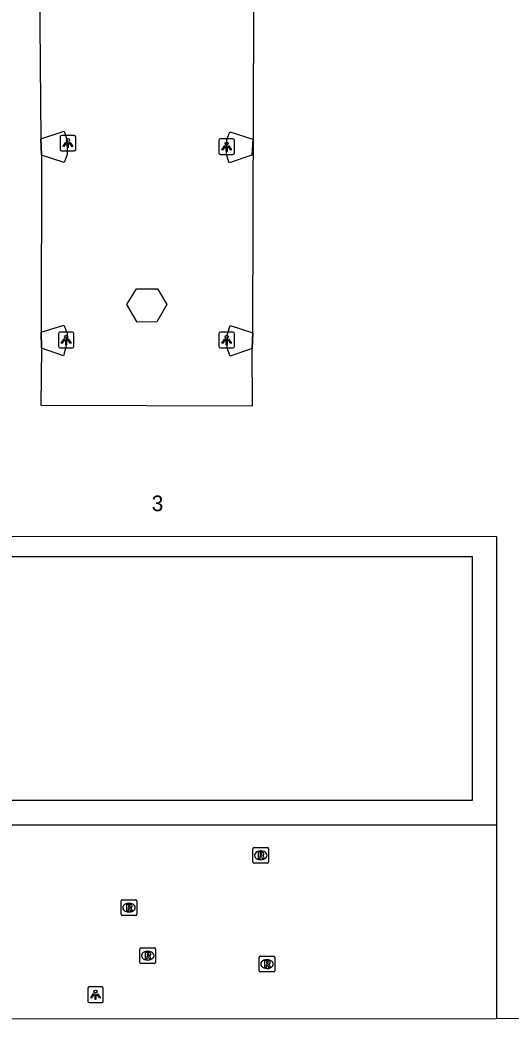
# Model space of a CAD drawing. Extents: x 161477 to 163040, y 383680 to 384868.
# Drawn here: x 161868 to 161899.5, y 384190.9 to 384254.9 of the extents above; entities that cross this region are included whole.
import ezdxf

# ---------------------------------------------------------------- set-up
doc = ezdxf.new("R2010")
doc.units = 0
for name, color, linetype in [('IMGEO_Lichtpunt', 7, 'Continuous'), ('IMGEO_Pand', 7, 'Continuous'), ('IMGEO_Pand_nummerreeks', 7, 'Continuous'), ('IMGEO_Pand_overbouw', 7, 'Continuous'), ('IMGEO_Rioolput', 7, 'Continuous'), ('IMGEO_Voetpad_gesloten', 7, 'Continuous'), ('IMGEO_Voetpad_open', 7, 'Continuous')]:
    doc.layers.add(name, color=color, linetype=linetype)

msp = doc.modelspace()

# ---------------------------------------------------------------- linework, layer by layer
at = {"layer": 'IMGEO_Lichtpunt'}
for p, q in [((161871.519, 384247.498), (161870.711, 384247.498)), ((161871.519, 384247.498), (161870.711, 384247.498)), ((161870.617, 384247.403), (161870.617, 384246.596)), ((161870.617, 384247.403), (161870.617, 384246.596)), ((161871.613, 384246.596), (161871.613, 384247.403)), ((161871.613, 384246.596), (161871.613, 384247.403)), ((161880.787, 384247.183), (161880.787, 384246.376)), ((161880.787, 384247.183), (161880.787, 384246.376)), ((161881.689, 384247.278), (161880.881, 384247.278)), ((161881.689, 384247.278), (161880.881, 384247.278)), ((161881.783, 384246.376), (161881.783, 384247.183)), ((161881.783, 384246.376), (161881.783, 384247.183)), ((161870.711, 384246.502), (161871.519, 384246.502)), ((161870.711, 384246.502), (161871.519, 384246.502)), ((161880.881, 384246.282), (161881.689, 384246.282)), ((161880.881, 384246.282), (161881.689, 384246.282)), ((161870.507, 384234.793), (161870.507, 384233.986)), ((161870.507, 384234.793), (161870.507, 384233.986)), ((161871.409, 384234.888), (161870.601, 384234.888)), ((161871.409, 384234.888), (161870.601, 384234.888)), ((161871.503, 384233.986), (161871.503, 384234.793)), ((161871.503, 384233.986), (161871.503, 384234.793)), ((161880.787, 384234.793), (161880.787, 384233.986)), ((161880.787, 384234.793), (161880.787, 384233.986)), ((161881.689, 384234.888), (161880.881, 384234.888)), ((161881.689, 384234.888), (161880.881, 384234.888)), ((161881.783, 384233.986), (161881.783, 384234.793)), ((161881.783, 384233.986), (161881.783, 384234.793)), ((161870.601, 384233.892), (161871.409, 384233.892)), ((161870.601, 384233.892), (161871.409, 384233.892)), ((161880.881, 384233.892), (161881.689, 384233.892)), ((161880.881, 384233.892), (161881.689, 384233.892)), ((161872.387, 384192.843), (161872.387, 384192.036)), ((161872.387, 384192.843), (161872.387, 384192.036)), ((161873.289, 384192.938), (161872.481, 384192.938)), ((161873.289, 384192.938), (161872.481, 384192.938)), ((161873.383, 384192.036), (161873.383, 384192.843)), ((161873.383, 384192.036), (161873.383, 384192.843)), ((161872.481, 384191.942), (161873.289, 384191.942)), ((161872.481, 384191.942), (161873.289, 384191.942))]:
    msp.add_line(p, q, dxfattribs=at)
for points in [[(161870.991, 384247.067), (161871.03, 384247.039), (161870.842, 384246.777), (161870.804, 384246.804), (161870.991, 384247.067)], [(161871.093, 384247.019), (161871.14, 384247.019), (161871.14, 384246.697), (161871.093, 384246.697), (161871.093, 384247.019)], [(161871.203, 384247.039), (161871.241, 384247.066), (161871.428, 384246.804), (161871.389, 384246.776), (161871.203, 384247.039)], [(161881.161, 384246.847), (161881.2, 384246.819), (161881.012, 384246.557), (161880.974, 384246.584), (161881.161, 384246.847)], [(161881.263, 384246.799), (161881.31, 384246.799), (161881.31, 384246.477), (161881.263, 384246.477), (161881.263, 384246.799)], [(161881.373, 384246.819), (161881.411, 384246.846), (161881.598, 384246.584), (161881.559, 384246.556), (161881.373, 384246.819)], [(161870.881, 384234.457), (161870.92, 384234.429), (161870.732, 384234.167), (161870.694, 384234.194), (161870.881, 384234.457)], [(161870.983, 384234.409), (161871.03, 384234.409), (161871.03, 384234.087), (161870.983, 384234.087), (161870.983, 384234.409)], [(161871.093, 384234.429), (161871.131, 384234.456), (161871.318, 384234.194), (161871.279, 384234.166), (161871.093, 384234.429)], [(161881.161, 384234.457), (161881.2, 384234.429), (161881.012, 384234.167), (161880.974, 384234.194), (161881.161, 384234.457)], [(161881.263, 384234.409), (161881.31, 384234.409), (161881.31, 384234.087), (161881.263, 384234.087), (161881.263, 384234.409)], [(161881.373, 384234.429), (161881.411, 384234.456), (161881.598, 384234.194), (161881.559, 384234.166), (161881.373, 384234.429)], [(161872.761, 384192.507), (161872.8, 384192.479), (161872.612, 384192.217), (161872.574, 384192.244), (161872.761, 384192.507)], [(161872.863, 384192.459), (161872.91, 384192.459), (161872.91, 384192.137), (161872.863, 384192.137), (161872.863, 384192.459)], [(161872.973, 384192.479), (161873.011, 384192.506), (161873.198, 384192.244), (161873.159, 384192.216), (161872.973, 384192.479)]]:
    msp.add_lwpolyline(points, dxfattribs=at)
for centre in [(161871.116, 384247.201), (161881.286, 384246.981), (161871.006, 384234.591), (161881.286, 384234.591), (161872.886, 384192.641)]:
    msp.add_circle(centre, 0.0994, dxfattribs=at)
for centre, start, end in [((161870.711, 384247.403), 90, 180), ((161870.711, 384247.403), 90, 180), ((161871.519, 384247.403), 0, 90), ((161871.519, 384247.403), 0, 90), ((161880.881, 384247.183), 90, 180), ((161880.881, 384247.183), 90, 180), ((161881.689, 384247.183), 0, 90), ((161881.689, 384247.183), 0, 90), ((161870.711, 384246.596), 180, 270), ((161870.711, 384246.596), 180, 270), ((161871.519, 384246.596), 270, 0), ((161871.519, 384246.596), 270, 360), ((161880.881, 384246.376), 180, 270), ((161880.881, 384246.376), 180, 270), ((161881.689, 384246.376), 270, 0), ((161881.689, 384246.376), 270, 360), ((161870.601, 384234.793), 90, 180), ((161870.601, 384234.793), 90, 180), ((161871.409, 384234.793), 0, 90), ((161871.409, 384234.793), 0, 90), ((161880.881, 384234.793), 90, 180), ((161880.881, 384234.793), 90, 180), ((161881.689, 384234.793), 0, 90), ((161881.689, 384234.793), 0, 90), ((161870.601, 384233.986), 180, 270), ((161870.601, 384233.986), 180, 270), ((161871.409, 384233.986), 270, 0), ((161871.409, 384233.986), 270, 360), ((161880.881, 384233.986), 180, 270), ((161880.881, 384233.986), 180, 270), ((161881.689, 384233.986), 270, 0), ((161881.689, 384233.986), 270, 360), ((161872.481, 384192.843), 90, 180), ((161872.481, 384192.843), 90, 180), ((161873.289, 384192.843), 0, 90), ((161873.289, 384192.843), 0, 90), ((161872.481, 384192.036), 180, 270), ((161872.481, 384192.036), 180, 270), ((161873.289, 384192.036), 270, 0), ((161873.289, 384192.036), 270, 360)]:
    msp.add_arc(centre, 0.0946, start, end, dxfattribs=at)
at = {"layer": 'IMGEO_Pand'}
for points in [[(161871.056, 384247.232), (161871.068, 384246.284), (161870.875, 384245.766), (161869.433, 384246.237), (161869.373, 384247.273), (161870.874, 384247.761), (161871.056, 384247.232)], [(161882.899, 384246.229), (161881.442, 384245.736), (161881.271, 384246.271), (161881.3, 384247.217), (161881.493, 384247.736), (161882.961, 384247.252), (161882.899, 384246.229)], [(161877.446, 384236.674), (161876.812, 384235.564), (161875.546, 384235.543), (161874.886, 384236.668), (161875.516, 384237.667), (161876.849, 384237.673), (161877.446, 384236.674)], [(161871.065, 384234.836), (161870.981, 384233.937), (161870.833, 384233.378), (161869.415, 384233.876), (161869.399, 384234.9), (161870.846, 384235.342), (161871.065, 384234.836)], [(161882.927, 384233.839), (161881.509, 384233.358), (161881.315, 384233.863), (161881.329, 384234.794), (161881.509, 384235.321), (161882.955, 384234.856), (161882.927, 384233.839)]]:
    msp.add_lwpolyline(points, dxfattribs=at)
at = {"layer": 'IMGEO_Pand_overbouw'}
for points in [[(161875.015, 384271.211), (161871.708, 384271.215), (161870.945, 384271.216), (161870.947, 384271.014), (161870.754, 384270.496), (161869.312, 384270.967), (161869.278, 384259.659), (161869.367, 384249.619), (161869.373, 384247.273), (161869.433, 384246.237), (161869.399, 384234.9), (161869.415, 384233.876), (161869.392, 384230.216), (161882.936, 384230.179), (161882.927, 384233.839), (161882.955, 384234.856), (161883.004, 384249.619)], [(161883.004, 384249.619), (161883.043, 384259.597), (161883.086, 384267.076), (161883.108, 384270.931), (161881.651, 384270.438), (161881.48, 384270.973), (161881.487, 384271.204), (161880.553, 384271.205), (161877.415, 384271.209)]]:
    msp.add_lwpolyline(points, dxfattribs=at)
at = {"layer": 'IMGEO_Rioolput'}
for p, q in [((161882.969, 384200.944), (161882.969, 384201.796)), ((161883.044, 384201.87), (161883.896, 384201.87)), ((161883.457, 384201.65), (161883.482, 384201.65)), ((161883.97, 384201.796), (161883.97, 384200.944)), ((161883.896, 384200.87), (161883.044, 384200.87)), ((161883.48, 384201.09), (161883.455, 384201.09)), ((161874.529, 384197.594), (161874.529, 384198.446)), ((161874.604, 384198.52), (161875.456, 384198.52)), ((161875.017, 384198.3), (161875.042, 384198.3)), ((161875.53, 384198.446), (161875.53, 384197.594)), ((161875.04, 384197.74), (161875.015, 384197.74)), ((161875.456, 384197.52), (161874.604, 384197.52)), ((161875.729, 384194.514), (161875.729, 384195.366)), ((161875.804, 384195.44), (161876.656, 384195.44)), ((161876.217, 384195.22), (161876.242, 384195.22)), ((161876.73, 384195.366), (161876.73, 384194.514)), ((161876.656, 384194.44), (161875.804, 384194.44)), ((161876.24, 384194.66), (161876.215, 384194.66)), ((161883.369, 384193.974), (161883.369, 384194.826)), ((161883.444, 384194.9), (161884.296, 384194.9)), ((161883.857, 384194.68), (161883.882, 384194.68)), ((161884.37, 384194.826), (161884.37, 384193.974)), ((161884.296, 384193.9), (161883.444, 384193.9)), ((161883.88, 384194.12), (161883.855, 384194.12))]:
    msp.add_line(p, q, dxfattribs=at)
for points in [[(161882.969, 384200.944), (161882.969, 384201.796)], [(161883.044, 384201.87), (161883.896, 384201.87)], [(161883.558, 384201.568), (161883.306, 384201.57), (161883.306, 384201.17)], [(161883.484, 384201.489), (161883.43, 384201.489), (161883.43, 384201.408)], [(161883.43, 384201.408), (161883.482, 384201.408)], [(161883.97, 384201.796), (161883.97, 384200.944)], [(161883.896, 384200.87), (161883.044, 384200.87)], [(161883.306, 384201.17), (161883.43, 384201.17), (161883.43, 384201.332), (161883.441, 384201.332)], [(161883.488, 384201.303), (161883.559, 384201.17), (161883.699, 384201.17), (161883.634, 384201.296)], [(161874.529, 384197.594), (161874.529, 384198.446)], [(161874.604, 384198.52), (161875.456, 384198.52)], [(161875.118, 384198.218), (161874.866, 384198.22), (161874.866, 384197.82)], [(161875.53, 384198.446), (161875.53, 384197.594)], [(161874.866, 384197.82), (161874.99, 384197.82), (161874.99, 384197.982), (161875.001, 384197.982)], [(161875.044, 384198.139), (161874.99, 384198.139), (161874.99, 384198.058)], [(161874.99, 384198.058), (161875.042, 384198.058)], [(161875.048, 384197.953), (161875.119, 384197.82), (161875.259, 384197.82), (161875.194, 384197.946)], [(161875.456, 384197.52), (161874.604, 384197.52)], [(161875.729, 384194.514), (161875.729, 384195.366)], [(161875.804, 384195.44), (161876.656, 384195.44)], [(161876.318, 384195.138), (161876.066, 384195.14), (161876.066, 384194.74)], [(161876.244, 384195.059), (161876.19, 384195.059), (161876.19, 384194.978)], [(161876.73, 384195.366), (161876.73, 384194.514)], [(161876.656, 384194.44), (161875.804, 384194.44)], [(161876.066, 384194.74), (161876.19, 384194.74), (161876.19, 384194.902), (161876.201, 384194.902)], [(161876.19, 384194.978), (161876.242, 384194.978)], [(161876.248, 384194.873), (161876.319, 384194.74), (161876.459, 384194.74), (161876.394, 384194.866)], [(161883.369, 384193.974), (161883.369, 384194.826)], [(161883.444, 384194.9), (161884.296, 384194.9)], [(161883.958, 384194.598), (161883.706, 384194.6), (161883.706, 384194.2)], [(161883.706, 384194.2), (161883.83, 384194.2), (161883.83, 384194.362), (161883.841, 384194.362)], [(161883.884, 384194.519), (161883.83, 384194.519), (161883.83, 384194.438)], [(161883.83, 384194.438), (161883.882, 384194.438)], [(161884.37, 384194.826), (161884.37, 384193.974)], [(161884.296, 384193.9), (161883.444, 384193.9)], [(161883.888, 384194.333), (161883.959, 384194.2), (161884.099, 384194.2), (161884.034, 384194.326)]]:
    msp.add_lwpolyline(points, dxfattribs=at)
for centre, radius, start, end in [((161883.046, 384201.794), 0.0765, 91.55205, 178.44795), ((161883.046, 384201.794), 0.0765, 91.55205, 178.44795), ((161883.466, 384201.597), 0.19, 274.7715, 282.96867), ((161883.49, 384201.393), 0.0964, 77.00612, 93.18647), ((161883.504, 384201.45), 0.0378, 276.66336, 79.67722), ((161883.557, 384201.458), 0.109, 350.36119, 89.41601), ((161883.555, 384201.458), 0.112, 277.58423, 350.98172), ((161883.894, 384201.794), 0.0765, 1.55205, 88.44795), ((161883.894, 384201.794), 0.0765, 1.55205, 88.44795), ((161883.046, 384200.946), 0.0765, 181.55205, 268.44795), ((161883.046, 384200.946), 0.0765, 181.55205, 268.44795), ((161883.44, 384201.279), 0.0533, 26.02933, 88.69889), ((161883.539, 384201.243), 0.108, 29.51342, 73.79051), ((161883.894, 384200.946), 0.0765, 271.55205, 358.44795), ((161883.894, 384200.946), 0.0765, 271.55205, 358.44795), ((161874.606, 384198.444), 0.0765, 91.55205, 178.44795), ((161874.606, 384198.444), 0.0765, 91.55205, 178.44795), ((161875.117, 384198.108), 0.109, 350.36119, 89.41601), ((161875.454, 384198.444), 0.0765, 1.55205, 88.44795), ((161875.454, 384198.444), 0.0765, 1.55205, 88.44795), ((161874.606, 384197.596), 0.0765, 181.55205, 268.44795), ((161874.606, 384197.596), 0.0765, 181.55205, 268.44795), ((161875, 384197.929), 0.0533, 26.02933, 88.69889), ((161875.026, 384198.247), 0.19, 274.7715, 282.96867), ((161875.05, 384198.043), 0.0964, 77.00612, 93.18647), ((161875.064, 384198.1), 0.0378, 276.66336, 79.67722), ((161875.115, 384198.108), 0.112, 277.58423, 350.98172), ((161875.099, 384197.893), 0.108, 29.51342, 73.79051), ((161875.454, 384197.596), 0.0765, 271.55205, 358.44795), ((161875.454, 384197.596), 0.0765, 271.55205, 358.44795), ((161875.806, 384195.364), 0.0765, 91.55205, 178.44795), ((161875.806, 384195.364), 0.0765, 91.55205, 178.44795), ((161876.25, 384194.963), 0.0964, 77.00612, 93.18647), ((161876.264, 384195.02), 0.0378, 276.66336, 79.67722), ((161876.317, 384195.028), 0.109, 350.36119, 89.41601), ((161876.315, 384195.028), 0.112, 277.58423, 350.98172), ((161876.654, 384195.364), 0.0765, 1.55205, 88.44795), ((161876.654, 384195.364), 0.0765, 1.55205, 88.44795), ((161875.806, 384194.516), 0.0765, 181.55205, 268.44795), ((161875.806, 384194.516), 0.0765, 181.55205, 268.44795), ((161876.2, 384194.849), 0.0533, 26.02933, 88.69889), ((161876.226, 384195.167), 0.19, 274.7715, 282.96867), ((161876.299, 384194.813), 0.108, 29.51342, 73.79051), ((161876.654, 384194.516), 0.0765, 271.55205, 358.44795), ((161876.654, 384194.516), 0.0765, 271.55205, 358.44795), ((161883.446, 384194.824), 0.0765, 91.55205, 178.44795), ((161883.446, 384194.824), 0.0765, 91.55205, 178.44795), ((161883.84, 384194.309), 0.0533, 26.02933, 88.69889), ((161883.866, 384194.627), 0.19, 274.7715, 282.96867), ((161883.89, 384194.423), 0.0964, 77.00612, 93.18647), ((161883.904, 384194.48), 0.0378, 276.66336, 79.67722), ((161883.957, 384194.488), 0.109, 350.36119, 89.41601), ((161883.955, 384194.488), 0.112, 277.58423, 350.98172), ((161883.939, 384194.273), 0.108, 29.51342, 73.79051), ((161884.294, 384194.824), 0.0765, 1.55205, 88.44795), ((161884.294, 384194.824), 0.0765, 1.55205, 88.44795), ((161883.446, 384193.976), 0.0765, 181.55205, 268.44795), ((161883.446, 384193.976), 0.0765, 181.55205, 268.44795), ((161884.294, 384193.976), 0.0765, 271.55205, 358.44795), ((161884.294, 384193.976), 0.0765, 271.55205, 358.44795)]:
    msp.add_arc(centre, radius, start, end, dxfattribs=at)
for centre, major_axis, ratio, start_param, end_param in [((161883.456, 384201.37), (-0.387, 0.002), 0.722429, 4.712389, 7.853982), ((161883.481, 384201.37), (-0.39, 0.002), 0.717154, 1.570796, 4.712389), ((161875.016, 384198.02), (-0.387, 0.002), 0.722429, 4.712389, 7.853982), ((161875.041, 384198.02), (-0.39, 0.002), 0.717154, 1.570796, 4.712389), ((161876.216, 384194.94), (-0.387, 0.002), 0.722429, 4.712389, 7.853982), ((161876.241, 384194.94), (-0.39, 0.002), 0.717154, 1.570796, 4.712389), ((161883.856, 384194.4), (-0.387, 0.002), 0.722429, 4.712389, 7.853982), ((161883.881, 384194.4), (-0.39, 0.002), 0.717154, 1.570796, 4.712389)]:
    msp.add_ellipse(centre, major_axis=major_axis, ratio=ratio, start_param=start_param, end_param=end_param, dxfattribs=at)
at = {"layer": 'IMGEO_Voetpad_gesloten'}
for points in [[(161830.757, 384236.661), (161851.028, 384236.605), (161851.028, 384221.813), (161898.561, 384221.807), (161898.56, 384203.307)], [(161897.024, 384220.497), (161849.443, 384220.497), (161849.443, 384235.11), (161830.753, 384235.161), (161825.183, 384235.177), (161825.183, 384204.896), (161897.024, 384204.896), (161897.024, 384220.497)], [(161898.56, 384203.307), (161831.783, 384203.307)]]:
    msp.add_lwpolyline(points, dxfattribs=at)
at = {"layer": 'IMGEO_Voetpad_open'}
for points in [[(161898.56, 384203.307), (161898.56, 384190.919)], [(161834.916, 384190.882), (161898.56, 384190.919)], [(161898.56, 384190.919), (161901.724, 384190.932)]]:
    msp.add_lwpolyline(points, dxfattribs=at)

# ---------------------------------------------------------------- texts
at = {"layer": 'IMGEO_Pand_nummerreeks'}
msp.add_text('3', height=1, rotation=359.9427, dxfattribs=at).set_placement((161876.483, 384223.423))

doc.saveas('drawing.dxf')
